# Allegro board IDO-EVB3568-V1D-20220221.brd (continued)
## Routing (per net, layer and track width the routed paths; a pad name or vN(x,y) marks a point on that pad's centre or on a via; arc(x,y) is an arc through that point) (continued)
GMAC0_TXD1_: length 62.4
  TOP w0.127: v2(92.43,56.72) 92.58,56.57 92.58,54.48 90.81,52.7 90.81,52.32 90.17,51.69 90.17,30.73 85.39,25.96 v2(84.96,25.96)
  BOTTOM w0.127: U24.17 109.57,70.27 110.67,69.16 110.67,65.73 107.17,62.23 103.19,62.23 102.81,62.61 101.41,62.61 100.78,61.98 98.3,61.98 93.04,56.72 v2(92.43,56.72) ; R198.2 v2(84.96,25.96)
GMAC0_TXD2: length 2
  TOP w0.127: M5.42 78.39,23.25 v2(78.92,22.72)
  BOTTOM w0.127: v2(78.92,22.72) 78.92,23.11 78.99,23.19 R201.1
GMAC0_TXD2_: length 67.1
  TOP w0.127: v2(90.91,55.65) 90.55,55.3 90.55,54.74 89.28,53.47 89.28,53.09 88.65,52.45 88.65,34.04 80.39,25.78 79.5,25.78 v2(78.99,25.27)
  BOTTOM w0.127: R201.2 v2(78.99,25.27) ; v2(90.91,55.65) 92.35,55.65 98.42,61.72 100.88,61.72 101.52,62.36 102.71,62.36 103.09,61.98 107.28,61.98 110.92,65.62 110.92,69.29 109.55,70.67 U24.16
GMAC0_TXD3: length 1.9
  TOP w0.127: v2(79.88,22.74) 79.39,23.24 M5.43
  BOTTOM w0.127: R202.1 80.01,23.27 79.88,23.15 v2(79.88,22.74)
GMAC0_TXD3_: length 67.3
  TOP w0.127: v2(79.63,25.25) 79.9,25.53 80.52,25.53 88.9,33.91 88.9,52.32 89.53,52.96 89.53,53.34 91.03,54.84 v2(91.03,55.09)
  BOTTOM w0.127: U24.15 109.53,71.07 111.18,69.42 111.18,65.52 107.38,61.72 102.98,61.72 102.6,62.1 101.62,62.1 100.99,61.47 98.55,61.47 92.2,55.12 91.06,55.12 v2(91.03,55.09) ; v2(79.63,25.25) 80.01,24.87 R202.2
GMAC0_TXEN: length 2.5
  TOP w0.127: v2(86.11,25.12) 85.83,25.12 85.39,24.68 M5.49
  BOTTOM w0.127: v2(86.11,25.12) 86.13,25.1 R204.1
GMAC0_TXEN_: length 60.5
  TOP w0.127: v2(92.68,57.86) 92.84,57.71 92.84,54.36 91.06,52.58 91.06,52.2 90.42,51.56 90.42,30.48 86.38,26.44 86.38,26.24 v2(86.11,25.96)
  BOTTOM w0.127: v2(92.68,57.86) 93.42,57.86 98.04,62.48 100.57,62.48 101.2,63.12 103.02,63.12 103.4,62.74 106.96,62.74 110.16,65.94 110.16,68.81 109.5,69.47 U24.19 ; R204.2 v2(86.11,25.96)
GMAC1_INT/PMEB_GPIO3_C1: length 8.9
  TOP w0.127: M5.110 87.39,69.58 87.96,69.01 93.81,69.01 v2(94.5,68.33)
  BOTTOM w0.127: v2(94.5,68.33) 94.5,68.06 94.66,67.9 R262.2
GMAC1_MCLKINOUT_M1: length 49.5
  TOP w0.127: v2(94.11,50.92) 93.22,50.03 93.22,41.91 93.73,41.4 93.73,38.48 94.36,37.85 94.36,37.21 95.33,36.24 M5.70
  BOTTOM w0.127: v2(94.11,50.92) 94.33,50.92 95.25,51.84 95.25,56.26 99.19,60.2 108.08,60.2 112.75,64.87 112.75,67.64 113.13,68.02 C194.2 113.18,68.02 113.67,68.51 113.78,68.51 114.15,68.88 R241.1 114.81,68.88 114.82,68.88 R240.1
GMAC1_MDC_M1: length 72
  TOP w0.127: M5.73 95.5,39.24 v2(95.25,39.24)
  BOTTOM w0.127: v2(95.25,39.24) 96.9,39.24 100.84,43.18 110.11,43.18 111.51,41.78 114.68,41.78 115.06,41.4 116.59,41.4 119.9,44.72 128.92,44.72 132.08,47.88 132.08,63.63 128.52,67.18 128.52,68.58 125.88,71.22 124.82,71.22 124.46,70.87 124.46,70.51 124.14,70.19 U25.13
GMAC1_MDIO_M1: length 72.2
  TOP w0.127: M5.72 95.11,38.24 94.73,38.62 v2(94.73,39.49)
  BOTTOM w0.127: v2(94.73,39.49) 94.73,39.88 95.11,40.26 97.16,40.26 100.58,43.69 110.36,43.69 111.76,42.29 114.93,42.29 115.32,41.91 116.33,41.91 119.63,45.21 119.66,45.21 119.67,45.22 128.66,45.22 131.57,48.13 131.57,63.39 128.02,66.95 128.02,68.33 125.93,70.41 125.22,70.41 R268.1 124.6,69.79 U25.14
GMAC1_RSTN_GPIO3_A6: length 8.5
  TOP w0.127: M5.121 76.39,70.7 75.33,71.75 v2(70.1,71.75)
  BOTTOM w0.127: v2(70.1,71.75) R267.1
GMAC1_RXCLK_M1: length 40.7
  TOP w0.127: v2(100.84,52.58) 100.71,52.45 100.71,51.05 100.08,50.42 98.04,50.42 97.86,50.24 M5.84
  BOTTOM w0.127: v2(100.84,52.58) 101.09,52.83 103.5,52.83 104.27,53.59 121.03,53.59 121.28,53.34 122.94,53.34 124.08,54.48 124.08,57.66 120.52,61.21 C211.2 119.81,61.83 119.76,61.88 R275.2
GMAC1_RXD0_M1: length 44.3
  TOP w0.127: M5.80 97.42,46.24 101.22,50.04 101.22,51.05 v2(101.47,51.31)
  BOTTOM w0.127: R271.2 121.67,63.91 122.19,63.39 122.19,61.33 124.97,58.55 124.97,54.1 123.19,52.32 104.39,52.32 103.38,51.31 v2(101.47,51.31)
GMAC1_RXD1_M1: length 42.5
  TOP w0.127: v2(101.71,50.8) 101.71,50.03 96.93,45.24 M5.79
  BOTTOM w0.127: R272.2 122.94,62.1 123.19,61.85 123.19,60.83 125.22,58.8 125.22,53.98 123.32,52.07 104.52,52.07 103.25,50.8 v2(101.71,50.8)
GMAC1_RXD2_M1: length 51.6
  TOP w0.127: M5.86 97.06,52.24 97.23,52.07 v2(99.95,52.07)
  BOTTOM w0.127: R273.2 122.96,64.34 123.57,63.73 123.57,60.83 128.27,56.13 128.27,49.4 127.11,48.25 103.5,48.25 100.46,51.29 100.46,51.56 v2(99.95,52.07)
GMAC1_RXD3_M1: length 51.4
  TOP w0.127: v2(99.95,51.44) 97.15,51.44 96.96,51.24 M5.85
  BOTTOM w0.127: R274.2 123.95,60.83 128.52,56.26 128.52,49.28 127.24,47.99 103.39,47.99 v2(99.95,51.44)
GMAC1_RXDV_CRS_M1: length 43.6
  TOP w0.127: v2(101.97,51.82) 101.97,51.42 102.11,51.28 102.11,49.91 96.43,44.24 M5.78
  BOTTOM w0.127: v2(101.97,51.82) 103.5,51.82 104.27,52.58 123.06,52.58 124.71,54.23 124.71,58.29 121.28,61.72 R276.2
GMAC1_TXCLK_M1: length 4.3
  TOP w0.127: M5.87 97.51,53.24 97.79,52.96 v2(98.83,52.96)
  BOTTOM w0.127: R253.1 99.06,52.32 99.27,52.53 C494.2 v2(98.83,52.96)
GMAC1_TXCLK_M1_: length 54.8
  BOTTOM w0.127: U25.20 124.25,67.39 125.35,66.29 125.35,60.83 129.29,56.9 129.29,48.77 127.76,47.24 102.49,47.24 101.22,48.51 101.22,49.15 100.2,50.16 C197.2 99.62,50.58 R253.2
GMAC1_TXD0_M1: length 3.9
  TOP w0.127: v2(98.93,49.15) 98.55,49.53 97.79,49.53 97.5,49.24 M5.83
  BOTTOM w0.127: R244.1 99.19,48.9 v2(98.93,49.15)
GMAC1_TXD0_M1_: length 56.5
  BOTTOM w0.127: U25.18 125.23,68.19 130.33,63.09 130.33,48.41 128.16,46.24 100.55,46.24 99.21,47.58 R244.2
GMAC1_TXD1_M1: length 2.9
  TOP w0.127: M5.82 97.39,48.24 v2(98.17,49.02)
  BOTTOM w0.127: R245.1 v2(98.17,49.02)
GMAC1_TXD1_M1_: length 58.6
  BOTTOM w0.127: R245.2 98.2,47.58 99.79,45.99 128.28,45.99 130.63,48.34 130.63,63.17 125.21,68.59 U25.17
GMAC1_TXD2_M1: length 5.3
  TOP w0.127: M5.89 97.18,55.24 98.17,54.24 v2(98.17,53.85)
  BOTTOM w0.127: v2(98.17,53.85) 98.17,52.29 97.79,51.91 R248.1
GMAC1_TXD2_M1_: length 63.7
  BOTTOM w0.127: R248.2 97.79,50.2 97.54,49.94 97.54,47.24 97.79,46.99 98.3,46.99 99.56,45.73 128.41,45.73 130.94,48.26 130.94,63.25 125.19,68.99 U25.16
GMAC1_TXD3_M1: length 2
  TOP w0.127: v2(97.54,53.85) 97.15,54.24 M5.88
  BOTTOM w0.127: R249.1 v2(97.54,53.85)
GMAC1_TXD3_M1_: length 66.9
  BOTTOM w0.127: R249.2 97.54,52.1 97.28,51.85 97.28,47.12 97.66,46.74 98.19,46.74 99.45,45.48 128.54,45.48 131.22,48.16 131.22,63.35 125.17,69.39 U25.15
GMAC1_TXEN_M1: length 5.2
  TOP w0.127: M5.81 97.78,47.24 v2(99.69,49.15)
  BOTTOM w0.127: v2(99.69,49.15) 100.2,48.64 R252.1
GMAC1_TXEN_M1_: length 54.5
  BOTTOM w0.127: R252.2 100.2,47.37 101.08,46.49 128.03,46.49 130.02,48.49 130.02,57.43 126.11,61.34 126.11,66.8 125.12,67.79 U25.19
HDMI_TX_CEC_PORT: length 7.5
  TOP w0.127: J18.13 31.15,91.16 32.26,90.04 D108.2 32.77,89 32.77,88.01 32.38,87.63 Q5.3
HDMI_TX_CLKN: length 24
  TOP w0.102: M5.153 44.39,70.29 44.06,70.62 v2(44.06,70.99) ; v2(30.73,85.47) 30.49,85.72 30.49,85.86 30.75,86.12 L26.2
  VCC w0.102: v2(30.73,85.47) 30.61,85.34 30.61,82.73 37.97,75.36 40.77,75.36 43.61,72.52 43.61,72.09 43.9,71.8 43.9,71.15 v2(44.06,70.99)
HDMI_TX_CLKN_: length 4.9
  TOP w0.102: J18.12 30.65,91.34 30.35,91.05 30.35,90.3 30.46,90.19 D48.6 D48.5 30.46,88.54 30.75,88.25 L26.3
HDMI_TX_CLKP: length 23.9
  TOP w0.102: v2(43.43,70.99) 43.43,70.74 43.39,70.69 M5.154 ; v2(29.97,85.47) 30.22,85.72 30.22,85.86 29.95,86.12 L26.1
  VCC w0.102: v2(29.97,85.47) 30.3,85.14 30.3,82.6 37.85,75.06 40.64,75.06 43.31,72.39 43.31,71.96 43.59,71.67 43.59,71.15 v2(43.43,70.99)
HDMI_TX_CLKP_: length 5
  TOP w0.102: L26.4 29.95,88.37 30.09,88.51 30.09,88.65 29.96,88.78 D48.4 D48.7 30.12,90.01 30.12,90.91 29.65,91.38 J18.10
HDMI_TX_D0N: length 23.9
  TOP w0.102: v2(42.25,70.93) 42.25,70.66 42.39,70.51 M5.155 ; L25.2 28.97,86.12 28.71,85.86 28.71,85.72 v2(28.96,85.47)
  VCC w0.102: v2(42.25,70.93) 42.04,71.14 42.04,72.26 40.08,74.22 37.46,74.22 28.73,82.96 28.73,85.24 v2(28.96,85.47)
HDMI_TX_D0N_: length 4.9
  TOP w0.102: L25.3 28.96,87.98 D48.2 D48.9 28.96,90.09 28.7,90.35 28.7,90.93 29.15,91.38 J18.9
HDMI_TX_D0P: length 23.9
  TOP w0.102: M5.156 41.39,70.6 41.53,70.74 v2(41.53,70.93) ; L25.1 28.18,86.12 28.44,85.86 28.44,85.72 v2(28.19,85.47)
  VCC w0.102: v2(41.53,70.93) 41.73,71.14 41.73,72.14 39.96,73.91 37.34,73.91 28.42,82.83 28.42,85.24 v2(28.19,85.47)
HDMI_TX_D0P_: length 5
  TOP w0.102: J18.7 28.15,91.36 28.46,91.04 D48.10 D48.1 28.46,88.51 28.57,88.4 28.57,88.26 28.28,87.97 L25.4
HDMI_TX_D1N: length 23.5
  TOP w0.102: M5.157 40.39,70.61 40.21,70.78 v2(40.21,70.99) ; v2(27.18,85.47) 26.93,85.72 26.93,85.86 27.2,86.12 L24.2
  VCC w0.102: v2(27.18,85.47) 26.95,85.24 26.95,83.08 36.96,73.08 39.12,73.08 40.01,72.18 40.01,71.2 v2(40.21,70.99)
HDMI_TX_D1N_: length 5.1
  TOP w0.102: L24.3 27.2,88.12 26.91,88.41 D47.5 D47.6 26.91,90.53 27.65,91.27 J18.6
HDMI_TX_D1P: length 23.5
  TOP w0.102: M5.158 39.39,70.63 39.5,70.74 v2(39.5,70.99) ; L24.1 26.4,86.12 26.66,85.86 26.66,85.72 v2(26.42,85.47)
  VCC w0.102: v2(39.5,70.99) 39.7,71.2 39.7,72.06 38.99,72.77 36.83,72.77 26.64,82.96 26.64,85.24 v2(26.42,85.47)
HDMI_TX_D1P_: length 5.1
  TOP w0.102: J18.4 26.65,91.34 26.86,91.13 26.86,90.86 26.59,90.6 26.59,90.21 26.41,90.03 D47.7 D47.4 26.41,88.78 26.64,88.55 26.64,88.35 26.4,88.11 L24.4
HDMI_TX_D2N: length 23
  TOP w0.102: v2(25.4,85.47) 25.15,85.72 25.15,85.86 25.42,86.12 L23.2 ; v2(38.31,70.93) 38.31,70.66 38.39,70.58 M5.159
  VCC w0.102: v2(25.4,85.47) 25.17,85.24 25.17,83.21 36.45,71.93 37.82,71.93 38.1,71.65 38.1,71.14 v2(38.31,70.93)
HDMI_TX_D2N_: length 5
  TOP w0.102: J18.3 26.15,91.3 25.91,91.06 25.78,91.06 25.41,90.69 D47.9 D47.2 25.41,87.98 L23.3
HDMI_TX_D2P: length 23
  TOP w0.102: v2(24.64,85.47) 24.88,85.72 24.88,85.86 24.62,86.12 L23.1 ; v2(37.59,70.93) 37.59,70.74 37.39,70.54 M5.160
  VCC w0.102: v2(37.59,70.93) 37.8,71.14 37.8,71.53 37.7,71.63 36.32,71.63 24.87,83.08 24.87,85.24 v2(24.64,85.47)
HDMI_TX_D2P_: length 4.9
  TOP w0.102: J18.1 25.13,92.59 25.13,90.28 24.91,90.06 D47.10 D47.1 24.91,88.41 24.62,88.12 L23.4
HDMI_TX_HPD_PORT: length 13.9
  TOP w0.127: J18.19 34.15,91.2 34.42,90.93 35.02,90.93 D111.2 37.11,89.51 37.97,88.65 37.97,82.8 38.18,82.6 R86.1 R85.2
HDMI_TX_HPDIN: length 16.8
  TOP w0.127: R85.1 39.04,78.69 40.64,77.09 42.19,77.09 48.41,70.87 49.02,70.87 49.39,70.5 M5.148
HDMI_TXDDC_SCL_PORT: length 9.4
  TOP w0.127: J18.15 32.15,90.79 32.89,90.04 33.53,90.04 33.66,89.92 D109.2 33.15,89 33.15,88.01 32.97,87.84 R82.2 32.97,86.87 33.1,86.74 34.31,86.74 34.54,86.51 Q3.3
HDMI_TXDDC_SDA_PORT: length 9.3
  TOP w0.127: Q4.3 36.7,86.87 36.19,87.38 R84.2 35.86,88.85 35.2,89.51 D110.2 34.68,89.51 33.89,90.3 33.15,90.3 32.65,90.8 J18.16
HDMITX_CEC_M0: length 22.7
  TOP w0.127: Q5.2 32.88,83.76 31.96,82.83 R87.2 32.59,82.17 34.42,82.17 40.26,76.33 41.78,76.33 46.39,71.72 M5.151
HOST_WAKE_BT: length 5.2
  TOP w0.127: U23.6 118.31,54.25 119.2,53.36 ; R162.2 121.49,53.36 121.01,53.85 119.69,53.85 119.2,53.36 ; 119.2,53.36 R164.1
HOST_WAKE_BT_H_GPIO3_A2: length 81.3
  TOP w0.127: v2(102.06,77.04) 102.82,76.28 102.82,76.02 103.53,75.31 111.76,75.31 113.28,73.79 113.28,68.71 114.71,67.28 114.71,66.52 115.9,65.33 117.68,65.33 v2(117.86,65.15) ; v2(93.51,67.57) 93.13,67.94 87.76,67.94 87.25,68.45 73.03,68.45 72.39,69.09 M5.125 ; R162.1 122.78,53.34 123.02,53.58 v2(123.02,54.53)
  BOTTOM w0.127: v2(123.02,54.53) 118.19,54.53 116.71,56.01 116.71,63.63 117.86,64.77 v2(117.86,65.15) ; v2(102.06,77.04) 101.75,77.34 97.66,77.34 96.14,75.82 96.14,70.61 94.11,68.58 94.11,67.78 93.9,67.57 v2(93.51,67.57)
HP_DET_H_GPIO0_C5: length 41.7
  TOP w0.127: M5.24 60.39,22.67 60.96,22.1 66.04,22.1 67.74,20.4 83.99,20.4 88.82,20.4 89.28,19.94 91.9,19.94 v2(92.08,19.76) ; v2(94.61,15.88) R72.2 C82.2 R74.1
  BOTTOM w0.127: v2(94.61,15.88) 94.61,16.38 93.47,17.53 93.47,17.91 92.08,19.3 v2(92.08,19.76)
HP_SNS: length 58.3
  TOP w0.254: R77.1 99.31,15.24 96.14,18.41 91.44,18.41 91.26,18.24 86.89,18.24 86.18,17.53 83.5,17.53 82.79,18.24 66.85,18.24 64.9,20.19 60.17,20.19 59.46,20.9 48.31,20.9 46.39,22.83 M5.10
HPL_OUT: length 58.4
  TOP w0.254: v2(92.43,17.91) 92.3,18.03 91.74,18.03 91.57,17.86 87.07,17.86 86.36,17.14 83.34,17.14 82.63,17.86 66.6,17.86 64.64,19.81 60.01,19.81 59.3,20.52 48.07,20.52 48.07,20.52 47.8,20.52 45.39,22.94 M5.9
  BOTTOM w0.254: C86.2 R73.1 94.49,12.45 93.6,13.34 93.6,16.21 92.43,17.37 v2(92.43,17.91)
HPR_OUT: length 60.4
  TOP w0.254: M5.11 47.39,22.84 48.95,21.28 59.61,21.28 60.33,20.57 65.15,20.57 67.11,18.62 82.95,18.62 83.66,17.91 85.98,17.91 86.69,18.62 91.01,18.62 91.19,18.8 97.28,18.8 101.55,14.53 C89.2 R76.1
HUB_RST_: length 5.1
  BOTTOM w0.127: U8.40 82.63,55.83 82.04,55.24 C60.2 R48.2 R39.2
I2C1_SCL: length 76.3
  TOP w0.127: v2(78.89,45.85) 81.41,43.33 81.41,43.05 v2(85.22,39.24) 85.85,38.61 85.85,35.43 78.99,28.57 71.12,28.57 70.1,27.56 67.94,27.56 67.18,26.8 67.18,25.66 68.39,24.46 M5.32 ; v2(114.13,40.78) 114.13,41.76 114.63,42.27 R316.2 R313.1
  BOTTOM w0.127: R344.1 v2(78.89,45.85) ; v2(114.13,40.78) 110.73,40.78 109.09,42.42 101.22,42.42 95.12,36.32 89.4,36.32 86.05,39.67 85.65,39.67 v2(85.22,39.24)
I2C1_SCL_RTC: length 2.2
  TOP w0.127: U34.6 116.42,42.64 116.07,42.29 R316.1
I2C1_SDA: length 83.4
  TOP w0.127: R312.1 R317.2 120.19,44.43 118.97,43.21 v2(118.97,42.24) ; M5.33 69.39,23.99 69,24.38 68.83,24.38 67.56,25.65 67.56,26.67 68.2,27.3 70.36,27.3 71.37,28.32 79.12,28.32 86.11,35.31 86.11,38.99 v2(85.85,39.24) 81.79,43.31 81.79,43.96 v2(78.89,46.86)
  BOTTOM w0.127: v2(85.85,39.24) 89.03,36.07 95.25,36.07 101.35,42.16 108.84,42.16 110.62,40.39 115.3,40.39 117.12,40.39 v2(118.97,42.24) ; R343.1 v2(78.89,46.86)
I2C1_SDA_RTC: length 2.3
  TOP w0.127: U34.5 118.32,43.29 118.96,43.93 118.96,44.06 119.33,44.43 R317.1
I2C2_SCL_M0: length 16.6
  TOP w0.127: M5.34 70.39,23.99 69.62,24.77 68.83,24.77 67.94,25.65 67.94,26.29 v2(68.45,26.8)
  BOTTOM w0.127: v2(68.45,26.8) 67.18,28.07 67.18,29.84 66.67,30.35 66.67,32.38 67.06,32.77 67.06,33.4 66.29,34.16 65.18,34.16 65.02,34.32 R320.1 65.05,34.75 65.42,35.12 65.52,35.12 66.02,35.61 R318.1
I2C2_SDA_M0: length 17.2
  TOP w0.127: M5.35 71.39,23.99 70.36,25.02 68.96,25.02 68.45,25.53 v2(68.45,26.16)
  BOTTOM w0.127: R319.1 R321.1 64.03,34.75 64.87,33.91 66.17,33.91 66.8,33.27 66.8,32.89 66.42,32.51 66.42,30.23 66.93,29.72 66.93,27.69 v2(68.45,26.16)
I2C3_SCL_M1: length 70.7
  TOP w0.127: v2(78.47,72.03) 78.71,72.26 79.86,72.26 80.57,71.55 82.35,71.55 83.39,70.51 M5.114 ; v2(73.03,27.79) 73.76,27.05 75.82,27.05 76.33,27.56 79.5,27.56 86.74,34.8 86.74,34.82 86.87,34.95 86.87,62.99 85.47,64.39 79.38,64.39 78.49,65.28 77.39,65.28 v2(77.14,65.53)
  BOTTOM w0.127: v2(77.14,65.53) 77.14,68 78.23,69.09 78.23,71.12 78.47,71.36 v2(78.47,72.03) 78.47,72.58 R109.1 ; R113.1 v2(73.03,27.79)
I2C3_SDA_M1: length 68.1
  TOP w0.127: v2(71.88,27.79) 72.87,26.8 75.95,26.8 76.45,27.3 79.63,27.3 87.12,34.8 87.12,54.23 90.3,57.4 90.3,61.9 v2(89.69,62.51) ; v2(80.77,71.98) 83.21,71.98 84.39,70.81 M5.113 84.39,69.41 84.81,68.99 87.48,68.99 87.76,68.71 90.63,68.71 v2(90.73,68.61)
  BOTTOM w0.127: v2(89.69,62.51) 89.97,62.79 89.97,62.79 90.73,63.55 v2(90.73,68.61) ; R114.1 v2(71.88,27.79) ; v2(80.77,71.98) R110.1
I2C4_SCL_M0: length 2.6
  TOP w0.127: v2(95.3,42.55) 95.61,42.24 M5.76
  BOTTOM w0.127: R147.1 R144.1 v2(95.3,42.55)
I2C4_SDA_M0: length 2.6
  TOP w0.127: M5.77 95.73,43.24 v2(95.3,43.66)
  BOTTOM w0.127: R146.1 R145.1 v2(95.3,43.66)
I2C5_SCL-HDMI: length 20.5
  TOP w0.127: Q3.2 35.04,83.45 34.97,83.38 R81.2 34.97,81.99 40.39,76.58 41.91,76.58 47.39,71.1 M5.150
I2C5_SDA-HDMI: length 20
  TOP w0.127: M5.149 48.39,70.48 42.04,76.83 40.51,76.83 37.13,80.22 R83.2 37.13,83.38 37.2,83.45 Q4.2
LAN0_A+: length 24.4
  TOP w0.102: v2(103.76,78.61) 103.96,78.82 104.11,78.82 104.27,78.66 104.27,77.78 105.95,76.1 111.02,76.1 111.86,76.94 111.86,82.14 112.65,82.93 J30.2
  BOTTOM w0.102: v2(103.76,78.61) 103.95,78.42 D72.6 104.2,77.27 104.2,76.89 103.27,75.97 R190.2
LAN0_A-: length 24.4
  TOP w0.102: v2(103.76,79.25) 103.96,79.04 104.2,79.04 104.5,78.75 104.5,77.88 106.05,76.33 110.93,76.33 111.63,77.03 111.63,82.24 112.42,83.03 112.42,84.43 112.07,84.78 111.38,84.78
  BOTTOM w0.102: 103.95,80.07 103.95,79.44 v2(103.76,79.25) ; 103.95,80.07 D72.1 ; 103.95,80.07 104.42,79.6 104.42,76.8 103.89,76.26 103.89,76.12 R189.2
LAN0_B+: length 28.3
  TOP w0.102: v2(106.17,79.25) 105.97,79.04 105.54,79.04 105.31,78.81 105.31,78.14 106.59,76.86 110.64,76.86 111.23,77.44 111.23,82.26 110.24,83.25 110.24,85.6 108.94,86.89 108.94,88.37 109.09,88.52 110.01,88.52 110.11,88.42 J30.4
  BOTTOM w0.102: D72.3 105.85,80.07 ; 105.85,80.07 105.85,79.57 v2(106.17,79.25) ; 105.85,80.07 105.38,79.6 105.38,76.07 105.28,75.97 R188.2
LAN0_B-: length 28.3
  TOP w0.102: 106.3,84.78 106.3,88.01 106.81,88.52 108.46,88.52 108.71,88.27 108.71,86.8 110.01,85.5 110.01,83.16 111,82.17 111,77.54 110.55,77.09 106.68,77.09 105.54,78.23 105.54,78.71 105.64,78.82 105.97,78.82 v2(106.17,78.61)
  BOTTOM w0.102: R187.2 105.89,75.97 105.61,76.26 105.61,77.27 D72.4 105.85,78.29 v2(106.17,78.61)
LAN0_C+: length 19.4
  TOP w0.102: J30.5 109.12,84.78 109.22,84.88 109.22,85.6 108.47,86.35 107.94,86.35 107.8,86.21 107.8,83.03 110.62,80.21 110.62,78.11 110.13,77.62 108.86,77.62 107.66,78.82 107.52,78.82 v2(107.31,78.61)
  BOTTOM w0.102: R186.2 107.53,75.97 107.7,76.13 107.7,77.46 D71.6 107.63,78.29 v2(107.31,78.61)
LAN0_C-: length 19.6
  TOP w0.102: v2(107.31,79.25) 107.52,79.04 107.76,79.04 108.95,77.85 110.04,77.85 110.39,78.2 110.39,80.11 107.57,82.93 J30.6
  BOTTOM w0.102: 107.63,79.94 107.63,79.57 v2(107.31,79.25) ; 107.63,79.94 D71.1 ; 107.63,79.94 108.11,79.47 108.11,76.91 107.95,76.76 107.95,76.33 R185.2
LAN0_D+: length 16.7
  TOP w0.102: J30.8 105.03,83.19 109.17,79.04 109.52,79.04 v2(109.73,79.25)
  BOTTOM w0.102: v2(109.73,79.25) 109.54,79.44 D71.3 109.16,80.22 109.06,80.12 109.06,76.87 109.59,76.33 109.59,76.19 R184.2
LAN0_D-: length 16.7
  TOP w0.102: v2(109.73,78.61) 109.52,78.82 109.07,78.82 104.8,83.09 104.8,86.08 104.39,86.49 103.38,86.49 103.03,86.14 103.03,85.51 103.76,84.78
  BOTTOM w0.102: R183.2 110.34,75.97 109.54,76.77 D71.4 109.54,78.42 v2(109.73,78.61)
LAN1_A+: length 29.9
  TOP w0.102: v2(120.91,80.9) 120.66,80.66 120.43,80.66 120.17,80.4 120.17,79.92 121.57,78.51 125.5,78.51 129.95,82.96 132.05,82.96 132.61,83.52 J31.2
  BOTTOM w0.102: R237.2 118.05,73.91 118.27,74.13 118.27,74.13 118.28,74.14 118.28,74.53 118.78,75.03 119.48,75.03 120.59,76.14 D74.6 120.83,76.62 120.83,77.47 120.11,78.19 120.11,80.3 120.43,80.62 120.63,80.62 v2(120.91,80.9)
LAN1_A-: length 29.9
  TOP w0.102: J31.3 131.34,86 131.57,86.23 132.33,86.23 132.38,86.18 132.38,83.62 131.95,83.19 129.85,83.19 125.41,78.74 121.67,78.74 120.4,80.01 120.4,80.3 120.52,80.43 120.66,80.43 v2(120.91,80.18)
  BOTTOM w0.102: R236.2 118.5,74.23 118.5,74.43 118.87,74.8 119.58,74.8 120.44,75.67 120.96,75.67 121.06,75.77 121.06,75.78 121.06,77.57 120.34,78.29 120.34,78.82 D74.1 120.34,79.32 120.34,80.21 120.52,80.39 120.7,80.39 v2(120.91,80.18)
LAN1_B+: length 30.5
  TOP w0.102: v2(121.79,80.18) 122.04,80.43 122.2,80.43 122.3,80.32 122.3,79.63 122.68,79.25 125.35,79.25 130.18,84.07 130.18,85.47 128.75,86.89 128.75,88.11 128.64,88.22 128.64,88.38 128.78,88.52 130.68,88.52 131.19,88.01 131.19,87.12 130.81,86.74 130.66,86.74 J31.4
  BOTTOM w0.102: R235.2 120.15,74.19 120.29,74.33 120.29,74.77 120.71,75.18 121.54,75.18 122.01,75.66 122.01,77.56 122.68,78.23 122.68,78.88 D74.3 122.74,79.32 122.74,79.83 122.16,80.41 122.02,80.41 v2(121.79,80.18)
LAN1_B-: length 30.5
  TOP w0.102: J31.7 126.26,87.91 126.87,88.52 128.02,88.52 128.52,88.01 128.52,86.8 129.95,85.38 129.95,84.17 125.25,79.48 122.78,79.48 122.53,79.72 122.53,80.42 122.29,80.66 122.04,80.66 v2(121.79,80.9)
  BOTTOM w0.102: v2(121.79,80.9) 122.06,80.63 122.25,80.63 122.97,79.92 122.97,78.19 122.24,77.47 122.24,76.62 D74.4 122.25,76.13 122.25,75.57 121.63,74.96 120.8,74.96 120.52,74.68 120.52,74.47 R234.2
LAN1_C+: length 19.9
  TOP w0.102: J31.5 128.8,85.57 128.52,85.85 127.89,85.85 127.76,85.72 127.76,82.55 125.22,80.01 123.99,80.01 123.57,80.43 123.43,80.43 v2(123.22,80.21)
  BOTTOM w0.102: R233.2 122.17,74.59 122.17,74.59 122.21,74.63 122.21,74.83 122.91,75.54 123.98,75.54 124.27,75.83 D73.6 124.52,76.62 124.52,77.67 123.79,78.39 123.79,80.23 123.63,80.39 123.39,80.39 v2(123.22,80.21)
LAN1_C-: length 19.9
  TOP w0.102: v2(123.19,80.9) 123.43,80.66 123.67,80.66 124.08,80.24 125.13,80.24 127.53,82.64 J31.6
  BOTTOM w0.102: R232.2 122.53,74.19 122.38,74.34 122.38,74.48 122.4,74.5 122.4,74.5 122.43,74.54 122.43,74.74 123.01,75.31 124.08,75.31 124.44,75.67 124.65,75.67 124.74,75.77 124.74,77.76 124.27,78.24 D73.1 124.02,79.32 124.02,80.32 123.7,80.64 123.44,80.64 v2(123.19,80.9)
LAN1_D+: length 19.5
  TOP w0.102: v2(124.33,80.9) 124.59,81.15 124.59,81.72 122.2,84.11 122.2,85.31 123.25,86.36 124.89,86.36 124.99,86.46 J31.8
  BOTTOM w0.102: v2(124.33,80.9) 124.59,80.64 124.59,80.39 124.94,80.04 126.14,80.04 126.42,79.76 126.42,79.32 D73.3 126.17,78.17 125.7,77.69 125.7,75.35 125.41,75.06 124.76,75.06 124.3,74.59 124.3,74.27 124.22,74.19 R231.2
LAN1_D-: length 19.6
  TOP w0.102: J31.9 124.52,85.58 124.52,86.03 124.41,86.13 123.34,86.13 122.43,85.22 122.43,84.2 124.82,81.81 124.82,81.13 v2(125.05,80.9)
  BOTTOM w0.102: R230.2 124.67,74.19 124.53,74.33 124.53,74.5 124.86,74.83 125.5,74.83 125.93,75.26 125.93,76.13 D73.4 125.93,76.62 125.93,77.6 126.65,78.32 126.65,79.85 126.24,80.26 125.04,80.26 124.82,80.49 124.82,80.67 v2(125.05,80.9)
LCM_VIO_EN: length 97.5
  TOP w0.127: v2(90.81,7.49) 91.19,7.87 91.19,10.81 90.17,11.82 v2(90.17,12.22) 89.68,12.71 Q7.1 ; v2(49.53,12.62) 49.14,13.01 Q10.1 ; v2(78.61,40.01) 79.12,39.5 79.12,30.73 v2(78.61,30.23)
  BOTTOM w0.127: v2(90.17,12.22) 90.58,12.22 90.89,12.53 90.89,12.99 91.31,13.41 91.31,22.35 89.53,24.13 89.53,25.15 88.9,25.78 88.9,26.42 87.63,27.69 84.71,27.69 82.04,30.35 79.39,30.35 79.26,30.23 v2(78.61,30.23) ; R359.1 v2(78.61,40.01) 81.07,40.01 82,40.93 U38.15 ; v2(49.53,12.62) 52.65,12.62 53.72,11.56 54.61,11.56 55.4,10.77 70.84,10.77 71.63,11.56 76.18,11.56 77.09,10.65 77.09,7.62 77.22,7.49 v2(90.81,7.49)
LVDS0_CLKN: length 28.7
  TOP w0.102: v2(23.58,14.24) 23.82,14 23.82,13.65 23.69,13.51 D68.5 D68.6 23.69,12.13 23.82,11.99 23.82,11.29 24.31,10.79 25.15,10.79 26.04,9.91 26.04,8.36 25.93,8.26 25.27,8.26 25.17,8.36 J26.15 ; U17.27 18.79,24.31 18.66,24.17 18.23,24.17 15.46,21.4 15.46,18.85 v2(15.28,18.67)
  GND w0.102: v2(23.58,14.24) 23.79,14.44 23.79,14.95 22.99,15.75 16.51,15.75 15.42,16.84 15.42,18.52 v2(15.28,18.67)
LVDS0_CLKP: length 28.7
  TOP w0.102: U17.28 18.79,23.81 18.65,23.94 18.32,23.94 15.69,21.31 15.69,18.85 v2(15.88,18.67) ; J26.16 25.17,7.93 25.27,8.03 26.03,8.03 26.26,8.27 26.26,10 25.24,11.02 24.41,11.02 24.05,11.38 24.05,11.99 24.19,12.12 D68.7 D68.4 24.19,13.51 24.05,13.65 24.05,14 v2(24.3,14.24)
  GND w0.102: v2(24.3,14.24) 24.09,14.44 24.09,15.07 23.11,16.05 16.64,16.05 15.73,16.96 15.73,18.52 v2(15.88,18.67)
LVDS0_D0N: length 28.8
  TOP w0.102: J26.7 33.17,8.36 33.27,8.26 33.93,8.26 34.04,8.36 34.04,9.91 32.49,11.46 28.61,11.46 28.37,11.69 28.37,11.99 28.24,12.12 D66.9 D66.2 28.24,13.48 28.37,13.62 28.37,14.07 v2(28.13,14.32) ; U17.33 18.75,21.31 18.61,21.17 18.31,21.17 18.02,20.87 18.02,20.02 18.11,19.93 18.11,19.42 v2(17.95,19.26)
  GND w0.102: v2(28.13,14.32) 28.33,14.52 28.33,15.3 25.22,18.41 18.44,18.41 18.08,18.77 18.08,19.12 v2(17.95,19.26)
LVDS0_D0P: length 28.8
  TOP w0.102: v2(18.52,19.26) 18.34,19.44 18.34,20.02 18.24,20.12 18.24,20.78 18.41,20.94 18.59,20.94 18.73,20.81 U17.34 ; v2(28.84,14.32) 28.6,14.07 28.6,13.62 28.74,13.49 D66.1 D66.10 28.74,12.1 28.6,11.96 28.6,11.79 28.7,11.68 32.58,11.68 34.26,10 34.26,8.27 34.03,8.03 33.27,8.03 33.17,7.93 J26.8
  GND w0.102: v2(18.52,19.26) 18.39,19.12 18.39,18.9 18.57,18.72 25.35,18.72 28.64,15.43 28.64,14.52 v2(28.84,14.32)
LVDS0_D1N: length 29.3
  TOP w0.102: v2(17.11,18.59) 17.3,18.78 17.3,21.11 18.36,22.17 18.64,22.17 18.77,22.31 U17.31 ; J26.9 31.17,8.36 31.27,8.26 31.88,8.26 32,8.39 32,10.16 31.47,10.69 27.69,10.69 26.87,11.51 26.87,11.74 26.74,11.88 D66.6 D66.5 26.74,13.48 26.87,13.61 26.87,14.05 v2(26.63,14.29)
  GND w0.102: v2(26.63,14.29) 26.83,14.5 26.83,14.95 24.18,17.6 17.65,17.6 17.25,18.01 17.25,18.46 v2(17.11,18.59)
LVDS0_D1P: length 29.3
  TOP w0.102: v2(27.34,14.29) 27.1,14.05 27.1,13.62 27.24,13.48 D66.4 D66.7 27.24,11.88 27.1,11.74 27.1,11.61 27.79,10.92 31.57,10.92 32.23,10.25 32.23,8.29 31.97,8.03 31.27,8.03 31.17,7.93 J26.10 ; U17.32 18.78,21.81 18.65,21.94 18.45,21.94 17.53,21.01 17.53,18.75 v2(17.69,18.59)
  GND w0.102: v2(17.69,18.59) 17.55,18.46 17.55,18.14 17.78,17.91 24.31,17.91 27.14,15.07 27.14,14.5 v2(27.34,14.29)
LVDS0_D2N: length 29.9
  TOP w0.102: U17.29 18.73,23.31 18.6,23.17 18.29,23.17 16.44,21.32 16.44,19.62 v2(16.26,19.43) ; v2(25.08,14.24) 25.32,14 25.32,13.62 25.19,13.48 D68.2 D68.9 25.19,12.15 25.32,12.01 25.32,11.76 25.88,11.2 26.03,11.2 27.17,10.06 29.97,10.06 30.1,9.93 30.1,8.45 29.91,8.26 29.27,8.26 29.17,8.36 J26.11
  GND w0.102: v2(16.26,19.43) 16.4,19.28 16.4,17.51 17.14,16.76 23.83,16.76 25.29,15.3 25.29,14.44 v2(25.08,14.24)
LVDS0_D2P: length 29.9
  TOP w0.102: v2(16.86,19.43) 16.67,19.62 16.67,21.22 18.39,22.94 18.64,22.94 18.78,22.81 U17.30 ; v2(25.8,14.24) 25.55,14 25.55,13.6 25.69,13.46 D68.1 D68.10 25.69,12.14 25.55,12.01 25.55,11.85 25.98,11.43 26.12,11.43 27.26,10.29 30.07,10.29 30.33,10.03 30.33,8.36 30,8.03 29.27,8.03 29.17,7.93 J26.12
  GND w0.102: v2(16.86,19.43) 16.71,19.28 16.71,17.63 17.27,17.07 23.95,17.07 25.59,15.43 25.59,14.44 v2(25.8,14.24)
LVDS0_D3N: length 29.2
  TOP w0.102: v2(14.26,19.43) 14.45,19.62 14.45,21.48 18.13,25.17 18.37,25.17 18.51,25.31 U17.25 ; J26.17 23.17,8.36 23.27,8.26 23.9,8.26 24,8.36 24,9.91 22.96,10.95 22.77,10.95 22.28,11.44 22.28,11.74 22.14,11.88 D69.9 D69.2 22.14,13.51 22.28,13.65 22.28,13.87 v2(22.03,14.11)
  GND w0.102: v2(14.26,19.43) 14.41,19.28 14.41,16.2 16,14.61 22.1,14.61 22.24,14.46 22.24,14.32 v2(22.03,14.11)
LVDS0_D3P: length 29.2
  TOP w0.102: v2(22.75,14.11) 22.51,13.87 22.51,13.65 22.64,13.51 D69.1 D69.10 22.64,11.88 22.51,11.74 22.51,11.53 22.86,11.18 23.06,11.18 24.23,10 24.23,8.27 24,8.03 23.27,8.03 23.17,7.93 J26.18 ; v2(14.86,19.43) 14.67,19.62 14.67,21.39 18.23,24.94 18.37,24.94 18.51,24.81 U17.26
  GND w0.102: v2(22.75,14.11) 22.54,14.32 22.54,14.59 22.22,14.91 16.13,14.91 14.71,16.33 14.71,19.28 v2(14.86,19.43)
LVDS1_CLKN: length 17.3
  TOP w0.102: J26.27 13.17,8.36 13.3,8.23 13.69,8.23 13.99,8.53 13.99,9.87 14.64,10.52 15.4,10.52 16.18,11.3 16.18,12.01 16.04,12.15 D70.9 D70.2 16.04,13.73 16.2,13.88 16.2,14.42 17.12,15.34 18.83,15.34 21.94,18.45 21.94,18.62 21.81,18.76 U17.41
LVDS1_CLKP: length 17.4
  TOP w0.102: J26.28 13.17,7.51 13.66,8 13.79,8 14.22,8.44 14.22,9.78 14.73,10.29 15.49,10.29 16.41,11.2 16.41,11.99 16.54,12.13 D70.10 D70.1 16.54,13.73 16.43,13.84 16.43,14.33 17.21,15.11 18.92,15.11 22.17,18.36 22.17,18.66 22.31,18.8 U17.42
LVDS1_D0N: length 15
  TOP w0.102: U17.47 24.81,18.76 24.94,18.62 24.94,18.54 20.78,14.38 20.78,13.86 20.64,13.73 D69.5 D69.6 20.64,12.07 20.78,11.94 20.78,11.35 22.1,10.03 22.1,8.58 21.78,8.26 21.52,8.26 21.44,8.17 21.3,8.17 21.17,8.3 J26.19
LVDS1_D0P: length 15
  TOP w0.102: J26.20 21.17,7.58 21.62,8.03 21.87,8.03 22.33,8.48 22.33,10.13 21.01,11.45 21.01,11.94 21.14,12.07 D69.7 D69.4 21.14,13.73 21.01,13.86 21.01,14.28 25.17,18.45 25.17,18.62 25.31,18.75 U17.48
LVDS1_D1N: length 14.9
  TOP w0.102: J26.21 19.17,8.36 19.4,8.13 19.56,8.13 20.07,8.64 20.07,10.29 19.23,11.12 19.23,11.74 19.09,11.88 D67.9 D67.2 19.09,13.48 19.25,13.63 19.25,13.76 23.94,18.45 23.94,18.63 23.81,18.77 U17.45
LVDS1_D1P: length 14.9
  TOP w0.102: J26.22 19.17,7.48 19.58,7.9 19.65,7.9 20.29,8.54 20.29,10.38 19.46,11.22 19.46,11.74 19.59,11.88 D67.10 D67.1 19.59,13.48 19.47,13.6 19.47,13.67 24.17,18.36 24.17,18.63 24.31,18.77 U17.46
LVDS1_D2N: length 15.5
  TOP w0.102: U17.43 22.81,18.8 22.94,18.66 22.94,18.46 19.06,14.58 17.97,14.58 17.73,14.34 17.73,13.62 17.59,13.48 D67.5 D67.6 17.59,11.88 17.73,11.74 17.73,11.48 18.03,11.18 18.03,8.64 17.66,8.26 17.59,8.26 17.5,8.17 17.36,8.17 17.17,8.36 J26.23
LVDS1_D2P: length 15.5
  TOP w0.102: U17.44 23.31,18.78 23.17,18.65 23.17,18.37 19.15,14.35 18.06,14.35 17.96,14.25 17.96,13.61 18.09,13.48 D67.4 D67.7 18.09,11.88 17.96,11.74 17.96,11.58 18.26,11.27 18.26,8.54 17.75,8.03 17.68,8.03 17.17,7.51 J26.24
LVDS1_D3N: length 18
  TOP w0.102: U17.39 20.81,18.82 20.94,18.68 20.94,18.52 18.52,16.1 16.74,16.1 14.69,14.05 14.69,13.87 14.54,13.73 D70.5 D70.6 14.54,12.09 14.68,11.95 14.68,11.65 14.46,11.43 13.39,11.43 11.99,10.03 11.99,8.44 11.81,8.26 11.62,8.26 11.52,8.16 11.37,8.16 11.17,8.36 J26.29
LVDS1_D3P: length 18.1
  TOP w0.102: U17.40 21.31,18.82 21.17,18.68 21.17,18.43 18.62,15.88 16.83,15.88 14.92,13.96 14.92,13.86 15.04,13.73 D70.4 D70.7 15.04,12.09 14.91,11.95 14.91,11.56 14.55,11.2 13.49,11.2 12.22,9.94 12.22,8.34 11.91,8.03 11.71,8.03 11.17,7.48 J26.30
LVDS_ON_: length 21
  TOP w0.127: v2(35.69,10.92) 35.51,10.92 R128.2 33.86,13.02 34.04,13.2 R127.2 34.49,13.79 34.56,13.72 Q8.2
  BOTTOM w0.127: J27.4 47.62,7.9 42.62,7.9 41.27,9.25 41.27,9.78 40.59,10.46 36.14,10.46 v2(35.69,10.92)
LVDS_PWM5: length 97.5
  TOP w0.127: v2(29.72,12.75) 29.86,12.9 U18.2 30.93,12.9 R130.1 ; v2(65.41,28.57) 63.58,28.57 59.39,24.38 M5.23
  BOTTOM w0.127: v2(65.41,28.57) 65.41,27.05 67.18,25.27 67.18,16.64 67.56,16.26 67.94,16.26 69.53,14.67 69.98,14.67 70.23,14.41 70.23,12.7 69.98,12.45 56.26,12.45 54.48,14.22 46.81,14.22 45.34,12.75 v2(29.72,12.75) 29.64,12.67 14.12,12.67 11.05,15.75 11.05,17.4 11.81,18.16 R102.1
LVDS_PWM5_: length 18.7
  TOP w0.127: v2(34.92,10.92) 34.16,10.92 32.84,12.25 U18.4 32.08,12.25 31.82,12.5 R130.2
  BOTTOM w0.127: J27.3 47.22,6.25 45.97,7.49 42.39,7.49 40.77,9.12 40.77,9.65 40.21,10.21 35.64,10.21 v2(34.92,10.92)
LVDS_VIO: length 8.6
  TOP w1.016: J25.6 43.34,11.25 43.37,11.28 43.37,11.68 Q9.2 ; J25.2 51.34,11.29 50.98,11.65 50.98,12.48 C138.2 ; J25.4 47.34,11.02 47.37,11.05
LVDS_VIO_: length 8.7
  TOP w0.432: J26.1 40.09,9.14 ; J26.1 39.17,10.07 ; J26.1 38.24,9.14 ; J26.1 39.17,8.22 ; 37.99,9.14 J26.3 37.17,9.97 ; J26.2 39.99,7.14 ; J26.2 38.34,7.14 ; J26.2 39.17,7.97 ; J26.2 39.17,6.32
MIC1_INN: length 62.9
  TOP w0.254: v2(89.66,19.15) 88.96,19.15 88.58,19.53 86.51,19.53 85.64,18.67 84.07,18.67 83.29,19.46 67.54,19.46 65.66,21.34 60.68,21.34 59.96,22.05 49.64,22.05 49.39,22.3 M5.13 ; J15.4 94,5.57 92.2,7.37 92.2,11.99 90.38,13.82 D41.1 R68.1 v2(89.66,14.99) R70.1
  BOTTOM w0.254: v2(89.66,14.99) 89.28,15.37 89.28,18.77 v2(89.66,19.15)
MIC1_INP: length 111.9
  TOP w0.254: v2(88.39,19.08) 86.59,19.08 85.8,18.29 83.82,18.29 83.03,19.08 67.28,19.08 65.41,20.95 60.52,20.95 59.81,21.67 49.33,21.67 48.39,22.6 M5.12
  TOP w0.305: J16.2 134.77,16.1 D42.1 134.83,17.45 C84.2 R78.2 v1(134.11,19.68)
  BOTTOM w0.254: v2(88.39,19.08) 88.39,12.73 94.37,6.76 94.59,6.76 94.64,6.71 102.97,6.71 105.03,8.76 125.76,8.76 134.11,17.11 v1(134.11,19.68)
MIPI_CAM0_PDN_L_GPIO2_C1: length 115.3
  TOP w0.127: M5.53 89.39,24 v2(88.87,24.51) ; v2(23.04,64.06) 21.97,62.99 21.08,62.99 20.91,62.82 R142.1 ; v2(39.62,68.33) 38.1,66.8 38.1,62.28 38.89,61.49 72.11,61.49 76.83,56.77 76.83,31.5 v2(76.33,30.99)
  BOTTOM w0.127: v2(88.87,24.51) 88.87,25.04 88.39,25.53 88.39,26.16 87.38,27.18 84.69,27.18 84.46,27.18 82.42,29.21 78.11,29.21 v2(76.33,30.99) ; v2(39.62,68.33) 38.1,69.85 37.47,69.85 36.32,70.99 28.45,70.99 23.04,65.58 v2(23.04,64.06)
MIPI_CSI_CLKN: length 4.6
  TOP w0.102: J28.17 25.25,65.8 25.17,65.92 25.2,66.09 25.3,66.19 26.74,66.19 27.36,66.81 27.56,66.81 27.66,66.71 27.66,66.52 27.76,66.42 R141.2
MIPI_CSI_CLKP: length 4.7
  TOP w0.102: J28.18 25.08,66.3 25.2,66.42 26.64,66.42 27.26,67.04 27.56,67.04 27.66,67.14 27.66,67.34 27.76,67.44 R140.2
MIPI_CSI_D0N: length 4.8
  TOP w0.102: R133.2 27.76,62.23 27.66,62.33 27.66,62.52 27.56,62.62 27.2,62.62 26.64,63.18 25.15,63.18 25.02,63.04 25.02,62.9 25.15,62.77 25.94,62.77 J28.11
MIPI_CSI_D0P: length 4.7
  TOP w0.102: J28.12 24.12,63.41 26.74,63.41 27.29,62.85 27.56,62.85 27.66,62.95 27.66,63.14 27.76,63.25 R132.2
MIPI_CSI_D1N: length 4.7
  TOP w0.102: R135.2 27.76,64.39 27.66,64.49 27.66,64.68 27.56,64.78 27.34,64.78 26.76,64.21 24.11,64.21 J28.14
MIPI_CSI_D1P: length 4.6
  TOP w0.102: J28.15 25.28,64.8 25.1,64.62 25.1,64.52 25.17,64.44 26.67,64.44 27.24,65.01 27.56,65.01 27.66,65.11 27.66,65.3 27.76,65.41 R134.2
MIPI_CSI_D2N: length 5.7
  TOP w0.102: J28.20 25.04,67.3 25.14,67.19 26.81,67.19 27.08,67.46 27.08,68.51 27.42,68.85 27.56,68.85 27.66,68.75 27.66,68.55 27.76,68.45 R137.2
MIPI_CSI_D2P: length 5.8
  TOP w0.102: R136.2 27.76,69.47 27.66,69.37 27.66,69.18 27.56,69.08 27.32,69.08 26.85,68.6 26.85,67.56 26.71,67.42 25.24,67.42 25.08,67.58 25.08,67.72 25.18,67.81 25.96,67.81 J28.21
MIPI_CSI_D3N: length 5.5
  TOP w0.102: R139.2 27.76,70.48 27.66,70.59 27.66,70.78 27.56,70.88 27.16,70.88 27.05,70.77 27.05,70.23 26.34,69.52 25.42,69.52 25.15,69.25 25.15,68.93 25.27,68.8 J28.23
MIPI_CSI_D3P: length 5.5
  TOP w0.102: R138.2 27.76,71.5 27.66,71.4 27.66,71.21 27.56,71.11 27.06,71.11 26.82,70.87 26.82,70.33 26.25,69.75 25.32,69.75 24.88,69.3 J28.24
MIPI_CSI_RX_CLK0N: length 12.4
  TOP w0.102: R141.1 29.41,66.83 30.39,66.83 31.24,65.97 31.24,61.78 33.4,59.62 34.61,59.62 35,59.24 M5.170
MIPI_CSI_RX_CLK0P: length 12.4
  TOP w0.102: M5.169 34.99,60.24 34.6,59.85 33.49,59.85 31.47,61.87 31.47,66.07 30.48,67.06 29.39,67.06 R140.1
MIPI_CSI_RX_D0N: length 11.7
  TOP w0.102: M5.162 35,67.24 34.61,67.62 34.24,67.62 v2(34,67.38) ; v2(30.83,65.83) 30.58,65.58 30.58,63.47 29.73,62.62 29.4,62.62 R133.1
  BOTTOM w0.102: v2(30.83,65.83) 30.58,66.07 30.58,66.33 30.83,66.57 32.28,66.57 32.61,66.9 32.61,67.66 32.81,67.86 33.19,67.86 33.4,67.64 33.73,67.64 v2(34,67.38)
MIPI_CSI_RX_D0P: length 11.7
  TOP w0.102: M5.161 35.01,68.24 34.63,67.85 34.24,67.85 v2(34,68.1) ; v2(30.11,65.83) 30.35,65.58 30.35,63.57 29.64,62.85 29.4,62.85 R132.1
  BOTTOM w0.102: v2(34,68.1) 33.77,67.87 33.5,67.87 33.28,68.08 32.72,68.08 32.38,67.75 32.38,67 32.19,66.8 30.73,66.8 30.35,66.42 30.35,66.07 v2(30.11,65.83)
MIPI_CSI_RX_D1N: length 12.2
  TOP w0.102: v2(34.2,65.38) 34.44,65.62 34.61,65.62 34.99,65.24 M5.164 ; v2(29.86,64.54) 29.62,64.78 29.4,64.78 R135.1
  BOTTOM w0.102: v2(34.2,65.38) 34.02,65.56 33.69,65.56 33.43,65.81 31.75,65.81 31.62,65.68 31.62,65.43 31.75,65.3 33.11,65.3 33.38,65.04 33.38,64.52 33.11,64.26 31.37,64.26 30.85,64.78 30.1,64.78 v2(29.86,64.54)
MIPI_CSI_RX_D1P: length 12.3
  TOP w0.102: v2(34.2,66.1) 34.44,65.85 34.58,65.85 34.97,66.24 M5.163 ; v2(29.86,65.26) 29.62,65.01 29.4,65.01 R134.1
  BOTTOM w0.102: v2(34.2,66.1) 33.89,65.79 33.78,65.79 33.53,66.04 31.66,66.04 31.39,65.78 31.39,65.33 31.66,65.07 33.02,65.07 33.15,64.95 33.15,64.62 33.02,64.49 31.46,64.49 30.94,65.01 30.1,65.01 v2(29.86,65.26)
MIPI_CSI_RX_D2N: length 10.7
  TOP w0.102: M5.166 35.04,63.24 34.62,63.65 33.88,63.65 33.27,64.26 33.27,66.93 31.88,68.33 30.48,68.33 29.96,68.85 29.4,68.85 R137.1
MIPI_CSI_RX_D2P: length 10.6
  TOP w0.102: R136.1 29.4,69.08 30.05,69.08 30.57,68.55 31.97,68.55 33.5,67.02 33.5,64.36 33.98,63.88 34.65,63.88 35,64.24 M5.165
MIPI_CSI_RX_D3N: length 14.5
  TOP w0.102: v2(31.19,67.76) 31.43,67.51 31.43,67.25 32.28,66.4 32.28,62.97 33.63,61.62 34.64,61.62 35.03,61.24 M5.168 ; v2(31.18,68.96) 31.42,69.2 31.42,69.48 30.02,70.88 29.4,70.88 R139.1
  BOTTOM w0.102: v2(31.19,67.76) 31.43,68 31.43,68.7 v2(31.18,68.96)
MIPI_CSI_RX_D3P: length 14.5
  TOP w0.102: M5.167 35.03,62.24 34.65,61.85 33.72,61.85 32.51,63.06 32.51,66.49 31.66,67.34 31.66,67.51 v2(31.9,67.76) ; R138.1 29.4,71.11 30.11,71.11 31.65,69.57 31.65,69.2 v2(31.89,68.96)
  BOTTOM w0.102: v2(31.9,67.76) 31.66,68 31.66,68.72 v2(31.89,68.96)
MIPI_DSI_TX0_CLKN: length 73.6
  TOP w0.102: U17.19 22.31,26.6 22.44,26.74 22.44,26.94 23.85,28.35 25.17,28.35 25.63,28.8 25.68,28.8 26.16,29.29 v2(26.16,29.46) ; v2(42.03,66.17) 41.78,66.41 41.78,66.51 41.88,66.61 42.21,66.61 42.41,66.42 52.7,66.42 55,68.72 55,68.97 55.39,69.36 M5.142
  GND w0.102: v2(26.16,29.46) 25.96,29.26 25.78,29.26 25.65,29.39 25.65,30.99 27.01,32.35 27.16,32.35 27.29,32.21 27.69,32.21 28.01,32.53 28.01,32.93 27.87,33.07 27.87,33.21 28.02,33.35 28.16,33.35 28.36,33.15 28.76,33.15 29.08,33.48 29.08,33.87 28.88,34.07 28.88,34.21 29.02,34.36 29.17,34.36 29.43,34.1 29.83,34.1 30.15,34.42 30.15,34.81 29.89,35.08 29.89,35.22 30.05,35.38 31.95,35.38 41.83,45.26 41.83,46.61 42.8,47.57 42.8,64.95 42.09,65.66 41.98,65.66 41.82,65.82 41.82,65.96 v2(42.03,66.17)
  BOTTOM w0.102: v2(26.16,29.46) 26.41,29.22 26.56,29.22 26.82,28.96 26.82,28.8 27.47,28.16 27.47,27.82 R98.1
MIPI_DSI_TX0_CLKN_: length 5.6
  BOTTOM w0.102: J22.27 27.79,22.07 27.65,22.21 27.65,22.76 27.25,23.16 27.25,23.39 27.39,23.53 D53.9 D53.2 27.39,25.16 27.25,25.29 27.25,25.42 27.48,25.65 27.48,26.14 R98.2
MIPI_DSI_TX0_CLKP: length 73.4
  TOP w0.102: M5.143 54.39,69.36 54.77,68.97 54.77,68.81 52.61,66.65 52.31,66.65 52.18,66.78 51.87,66.78 51.75,66.65 51.44,66.65 51.31,66.78 51.01,66.78 50.88,66.65 50.58,66.65 50.45,66.78 50.15,66.78 50.02,66.65 42.5,66.65 42.31,66.84 41.79,66.84 41.55,66.61 41.55,66.41 v2(41.31,66.17) ; v2(26.16,28.75) 26.13,28.78 25.98,28.78 25.77,28.57 25.72,28.57 25.27,28.12 23.95,28.12 22.67,26.84 22.67,26.74 22.81,26.6 U17.18
  GND w0.102: v2(41.31,66.17) 41.52,65.96 41.52,65.69 41.85,65.35 41.96,65.35 42.49,64.82 42.49,47.7 41.53,46.74 41.53,45.39 31.83,35.69 29.92,35.69 29.58,35.35 29.58,34.95 29.84,34.69 29.84,34.54 29.7,34.4 29.56,34.4 29.29,34.66 28.9,34.66 28.58,34.34 28.58,33.94 28.78,33.75 28.78,33.6 28.63,33.46 28.49,33.46 28.29,33.66 27.89,33.66 27.57,33.34 27.57,32.94 27.71,32.8 27.71,32.66 27.56,32.52 27.42,32.52 27.28,32.65 26.89,32.65 25.35,31.11 25.35,29.26 25.65,28.95 25.96,28.95 v2(26.16,28.75)
  BOTTOM w0.102: v2(26.16,28.75) 26.41,28.99 26.46,28.99 26.59,28.86 26.59,28.71 27.24,28.06 27.24,27.82 R97.1
MIPI_DSI_TX0_CLKP_: length 5.6
  BOTTOM w0.102: J22.26 27.29,22.07 27.42,22.21 27.42,22.67 27.02,23.06 27.02,23.38 26.89,23.52 D53.10 D53.1 26.89,25.16 27.02,25.29 27.02,25.52 27.25,25.75 27.25,26.11 R97.2
MIPI_DSI_TX0_D0N: length 73
  TOP w0.102: v2(30.19,29.2) 29.93,28.95 29.71,28.95 28.78,28.02 27.44,28.02 26.45,27.03 24.74,27.03 24.44,26.73 24.44,26.47 24.31,26.33 U17.15 ; v2(44.03,68.2) 43.79,68.44 43.79,68.51 43.89,68.61 50.75,68.61 51,68.86 51,69.22 51.39,69.6 M5.146
  GND w0.102: v2(30.19,29.2) 29.98,28.99 29.68,28.99 29.46,29.21 29.46,30.43 30.4,31.37 31.35,31.37 31.92,30.79 32.32,30.79 32.64,31.12 32.64,31.51 31.67,32.49 31.67,32.63 31.81,32.78 31.95,32.78 32.93,31.8 33.32,31.8 33.65,32.12 33.65,32.52 32.67,33.49 32.67,33.64 39.88,40.84 42.49,40.84 44.37,42.72 44.37,67.3 43.83,67.85 43.83,67.99 v2(44.03,68.2)
  BOTTOM w0.102: v2(30.19,29.2) 30.43,28.96 30.8,28.96 31.69,28.07 31.69,27.77 R94.1
MIPI_DSI_TX0_D0N_: length 6.4
  BOTTOM w0.102: R94.2 31.69,26.18 31.69,25.92 31.37,25.6 30.88,25.6 30.66,25.38 30.66,24.28 D55.2 30.65,23.21 30.65,22.46 30.79,22.32 J22.33
MIPI_DSI_TX0_D0P: length 73.2
  TOP w0.102: M5.147 50.39,69.6 50.77,69.22 50.77,68.95 50.65,68.83 43.8,68.83 43.57,68.6 43.57,68.45 v2(43.32,68.2) ; U17.14 24.81,26.33 24.67,26.47 24.67,26.63 24.83,26.8 26.54,26.8 27.53,27.79 28.87,27.79 29.08,28 29.27,28 29.33,27.93 29.46,27.93 29.66,28.14 29.66,28.25 29.56,28.35 29.56,28.48 29.8,28.72 29.95,28.72 v2(30.19,28.48)
  GND w0.102: v2(30.19,28.48) 29.98,28.69 29.55,28.69 29.16,29.08 29.16,30.56 30.28,31.67 31.47,31.67 32.05,31.1 32.19,31.1 32.34,31.24 32.34,31.39 31.36,32.36 31.36,32.76 31.68,33.08 32.08,33.08 33.05,32.1 33.2,32.1 33.34,32.25 33.34,32.39 32.37,33.37 32.37,33.76 39.75,41.15 42.37,41.15 44.07,42.85 44.07,67.18 43.52,67.72 43.52,67.99 v2(43.32,68.2)
  BOTTOM w0.102: R93.1 31.46,27.77 31.46,27.98 30.71,28.73 30.43,28.73 v2(30.19,28.48)
MIPI_DSI_TX0_D0P_: length 6.4
  BOTTOM w0.102: J22.32 30.29,22.32 30.42,22.46 30.42,23.2 D54.2 30.43,24.31 30.43,25.48 30.78,25.83 31.27,25.83 31.46,26.02 31.46,26.18 R93.2
MIPI_DSI_TX0_D1N: length 72.9
  TOP w0.102: v2(28.01,29.3) 27.77,29.06 27.53,29.06 26.13,27.66 24.23,27.66 23.44,26.87 23.44,26.44 23.31,26.31 U17.17 ; v2(43.53,67.06) 43.28,67.3 43.28,67.47 43.4,67.59 52.01,67.59 53,68.58 53,69 53.39,69.39 M5.144
  GND w0.102: v2(28.01,29.3) 27.81,29.1 27.66,29.1 27.43,29.33 27.43,30.61 27.49,30.66 27.49,30.67 27.75,30.93 27.76,30.93 27.94,31.11 29.01,31.11 40.13,42.24 40.35,42.24 40.84,41.74 41.24,41.74 41.56,42.07 41.56,42.46 41.07,42.95 41.07,43.1 41.21,43.24 41.35,43.24 41.85,42.75 42.24,42.75 42.56,43.07 42.56,43.47 42.07,43.96 42.07,44.1 42.22,44.25 42.36,44.25 42.85,43.76 43.25,43.76 43.57,44.08 43.57,44.47 43.08,44.97 43.08,45.11 43.61,45.64 43.61,66.37 43.32,66.66 43.32,66.85 v2(43.53,67.06)
  BOTTOM w0.102: R96.1 29.62,27.81 29.62,28.24 28.8,29.06 28.26,29.06 v2(28.01,29.3)
MIPI_DSI_TX0_D1N_: length 6.1
  BOTTOM w0.102: R96.2 29.59,26.11 29.59,25.93 29.31,25.65 28.9,25.65 28.75,25.51 28.75,25.29 28.89,25.16 D53.5 D53.6 28.89,23.55 28.75,23.41 28.75,23.13 29.15,22.74 29.15,22.15 29.29,22.01 J22.30
MIPI_DSI_TX0_D1P: length 73
  TOP w0.102: v2(42.81,67.06) 43.05,67.3 43.05,67.56 43.31,67.82 48.46,67.82 48.59,67.94 48.9,67.94 49.02,67.82 49.33,67.82 49.45,67.94 49.76,67.94 49.89,67.82 50.19,67.82 50.32,67.94 50.62,67.94 50.75,67.82 51.92,67.82 52.77,68.67 52.77,69.02 52.39,69.4 M5.145 ; v2(28.01,28.59) 27.77,28.83 27.63,28.83 26.23,27.43 24.32,27.43 23.67,26.78 23.67,26.45 23.81,26.31 U17.16
  GND w0.102: v2(42.81,67.06) 43.01,66.85 43.01,66.54 43.31,66.24 43.31,45.77 42.77,45.24 42.77,44.84 43.27,44.35 43.27,44.2 43.12,44.06 42.98,44.06 42.49,44.55 42.09,44.55 41.77,44.23 41.77,43.83 42.26,43.34 42.26,43.2 42.12,43.06 41.97,43.06 41.48,43.55 41.08,43.55 40.76,43.22 40.76,42.83 41.25,42.34 41.25,42.19 41.11,42.05 40.97,42.05 40.47,42.54 40,42.54 28.88,31.42 27.81,31.42 27.63,31.24 27.63,31.24 27.18,30.79 27.18,30.79 27.13,30.73 27.13,29.2 27.54,28.79 27.81,28.79 v2(28.01,28.59)
  BOTTOM w0.102: v2(28.01,28.59) 28.26,28.83 28.7,28.83 29.39,28.14 29.39,27.84 R95.1
MIPI_DSI_TX0_D1P_: length 6.1
  BOTTOM w0.102: R95.2 29.36,26.14 29.36,26.03 29.22,25.88 28.8,25.88 28.52,25.6 28.52,25.29 28.39,25.16 D53.4 D53.7 28.39,23.52 28.52,23.38 28.52,23.04 28.92,22.64 28.92,22.17 28.79,22.04 J22.29
MIPI_DSI_TX0_D2N: length 73.1
  TOP w0.102: v2(24.26,29.45) 24.01,29.21 23.72,29.21 21.44,26.93 21.44,26.74 21.31,26.6 U17.21 ; v2(41.14,65.02) 40.89,65.27 40.89,65.37 41,65.47 41.39,65.47 41.56,65.3 52.8,65.3 55.85,68.35 56.54,68.35 57,68.81 57,69.07 57.39,69.45 M5.140
  GND w0.102: v2(24.26,29.45) 24.05,29.25 23.91,29.25 23.67,29.48 23.67,30.86 29.46,36.65 31.88,36.65 40.77,45.54 40.77,47.32 41.96,48.51 41.96,64.14 41.53,64.57 41.03,64.57 40.93,64.67 40.93,64.82 v2(41.14,65.02)
  BOTTOM w0.102: R100.1 25.34,27.82 25.34,28.2 24.99,28.55 24.99,28.98 24.79,29.18 24.53,29.18 v2(24.26,29.45)
MIPI_DSI_TX0_D2N_: length 5.7
  BOTTOM w0.102: J22.24 26.29,22.04 26.15,22.17 26.15,22.74 25.86,23.03 25.86,23.45 25.99,23.59 D52.6 D52.5 25.99,24.91 25.83,25.07 25.83,25.39 25.35,25.88 25.35,26.14 R100.2
MIPI_DSI_TX0_D2P: length 73.2
  TOP w0.102: v2(24.26,28.74) 24.01,28.98 23.82,28.98 21.67,26.83 21.67,26.74 21.81,26.6 U17.20 ; M5.141 56.39,69.43 56.77,69.05 56.77,68.91 56.45,68.58 55.75,68.58 52.7,65.53 52.4,65.53 52.27,65.66 51.97,65.66 51.84,65.53 51.54,65.53 51.41,65.66 51.1,65.66 50.98,65.53 50.67,65.53 50.55,65.66 50.24,65.66 50.11,65.53 41.66,65.53 41.49,65.7 40.9,65.7 40.67,65.46 40.67,65.27 v2(40.42,65.02)
  GND w0.102: v2(40.42,65.02) 40.63,64.82 40.63,64.55 40.91,64.27 41.4,64.27 41.66,64.01 41.66,48.64 40.46,47.45 40.46,45.67 31.75,36.96 29.34,36.96 23.37,30.99 23.37,29.36 23.78,28.94 24.05,28.94 v2(24.26,28.74)
  BOTTOM w0.102: R99.1 25.11,27.82 25.11,28.11 24.76,28.45 24.76,28.89 24.7,28.96 24.48,28.96 v2(24.26,28.74)
MIPI_DSI_TX0_D2P_: length 5.7
  BOTTOM w0.102: R99.2 25.12,26.11 25.12,25.78 25.6,25.3 25.6,25.08 25.49,24.97 D52.4 D52.7 25.49,23.58 25.63,23.44 25.63,22.94 25.92,22.64 25.92,22.21 25.79,22.07 J22.23
MIPI_DSI_TX0_D3N: length 73.3
  TOP w0.102: U17.23 20.31,26.6 20.44,26.74 20.44,27.11 21.21,27.88 21.21,28.32 21.95,29.06 22.21,29.06 v2(22.45,29.3) ; M5.138 59.39,69.47 59,69.09 59,68.78 57.78,67.56 56.2,67.56 52.9,64.26 41.02,64.26 40.92,64.16 40.92,64 v2(41.16,63.75)
  GND w0.102: v2(41.16,63.75) 40.96,63.55 40.96,48.7 39.88,47.62 39.88,45.97 31.45,37.54 28.96,37.54 21.97,30.56 21.97,29.2 22.07,29.1 22.25,29.1 v2(22.45,29.3)
  BOTTOM w0.102: R101.1 23.2,27.82 23.2,28.87 22.99,29.08 22.67,29.08 v2(22.45,29.3)
MIPI_DSI_TX0_D3N_: length 6.3
  BOTTOM w0.102: R101.2 23.2,26.13 23.2,25.95 23.39,25.76 23.93,25.76 24.36,25.32 24.36,25.05 24.49,24.92 D52.2 D52.9 24.49,23.53 24.36,23.39 24.36,22.66 24.65,22.36 24.65,22.17 24.79,22.04 J22.21
MIPI_DSI_TX0_D3P: length 73.4
  TOP w0.102: v2(40.45,63.75) 40.69,64 40.69,64.26 40.93,64.49 50.22,64.49 50.34,64.62 50.65,64.62 50.77,64.49 51.08,64.49 51.21,64.62 51.51,64.62 51.64,64.49 51.94,64.49 52.07,64.62 52.37,64.62 52.5,64.49 52.81,64.49 56.11,67.79 57.69,67.79 58.77,68.88 58.77,69.09 58.39,69.47 M5.139 ; v2(22.45,28.59) 22.21,28.83 22.04,28.83 21.44,28.23 21.44,27.79 20.67,27.02 20.67,26.74 20.81,26.6 U17.22
  GND w0.102: v2(40.45,63.75) 40.65,63.55 40.65,48.83 39.57,47.75 39.57,46.1 31.32,37.85 28.83,37.85 21.67,30.68 21.67,29.07 21.95,28.79 22.25,28.79 v2(22.45,28.59)
  BOTTOM w0.102: v2(22.45,28.59) 22.72,28.85 22.89,28.85 22.97,28.77 22.97,27.82 R92.1
MIPI_DSI_TX0_D3P_: length 6.3
  BOTTOM w0.102: J22.20 24.29,22.07 24.42,22.21 24.42,22.27 24.13,22.56 24.13,23.38 23.99,23.52 D52.10 D52.1 23.99,24.91 24.13,25.04 24.13,25.23 23.83,25.53 23.3,25.53 22.97,25.85 22.97,26.13 R92.2
MIPI_DSI_TX0_RST: length 5.4
  BOTTOM w0.127: J22.36 32.29,23.66 C118.2 33.22,24.6 R103.2
MIPI_DSI_TX1_CLKN: length 65.3
  TOP w0.102: v2(57.02,66.33) 57.27,66.57 61.75,66.57 63.88,68.71 64.64,68.71 65,69.07 65,69.34 65.39,69.73 M5.132
  BOTTOM w0.102: v2(57.02,66.33) 56.8,66.55 56.72,66.55 56.62,66.45 56.62,64.74 53.34,61.47 53.34,44.7 57.4,40.64 57.4,33.17 57.02,32.79 56.01,32.79 55.88,32.66 55.88,32.36 56.01,32.23 56.99,32.23 57.25,31.97 57.25,31.53 56.99,31.27 55.98,31.27 55.85,31.14 55.85,30.86 55.98,30.73 57.02,30.73 57.28,30.48 57.28,30.03 56.99,29.74 55.97,29.74 55.85,29.62 55.85,27.33 57.28,25.91 57.28,25.6 57.41,25.46 D58.2 D58.9 57.41,23.61 57.28,23.48 57.28,23.05 57.37,22.95 57.37,22.46 57.51,22.32 J23.27
MIPI_DSI_TX1_CLKP: length 65.3
  TOP w0.102: v2(57.02,67.05) 57.27,66.8 61.65,66.8 63.79,68.94 64.55,68.94 64.77,69.16 64.77,69.34 64.39,69.72 M5.133
  BOTTOM w0.102: J23.26 57.01,22.32 57.14,22.46 57.14,22.86 57.05,22.95 57.05,23.48 56.91,23.61 D58.10 D58.1 56.91,25.46 57.05,25.6 57.05,25.81 55.63,27.24 55.63,29.72 55.88,29.97 56.9,29.97 57.05,30.12 57.05,30.39 56.93,30.51 55.89,30.51 55.63,30.77 55.63,31.24 55.89,31.5 56.9,31.5 57.02,31.62 57.02,31.88 56.9,32 55.91,32 55.65,32.26 55.65,32.76 55.91,33.02 56.93,33.02 57.18,33.27 57.18,40.55 53.11,44.61 53.11,61.56 56.39,64.84 56.39,66.54 56.62,66.78 56.75,66.78 v2(57.02,67.05)
MIPI_DSI_TX1_D0N: length 64.8
  TOP w0.102: M5.136 61.39,69.39 61,69 61,68.78 v2(61.25,68.54)
  BOTTOM w0.102: J23.33 60.51,22.32 60.37,22.46 60.37,22.84 60.58,23.04 60.58,23.35 D61.2 60.63,24.41 60.63,25.88 60.37,26.14 59.69,26.14 59.56,26.26 59.56,26.57 59.69,26.7 60.42,26.7 60.68,26.96 60.68,27.4 60.42,27.66 59.69,27.66 59.56,27.79 59.56,28.09 59.69,28.22 60.42,28.22 60.68,28.48 60.68,28.92 60.42,29.18 58.93,29.18 58.78,29.34 58.78,29.59 58.9,29.72 60.32,29.72 60.58,29.98 60.58,30.45 60.32,30.71 58.93,30.71 58.8,30.84 58.8,31.11 58.93,31.24 60.33,31.24 60.58,31.5 60.58,31.97 60.32,32.23 59.03,32.23 58.93,32.33 58.93,41.15 54.86,45.21 54.86,60.83 61,66.97 61,68.29 v2(61.25,68.54)
MIPI_DSI_TX1_D0P: length 64.8
  TOP w0.102: v2(60.53,68.54) 60.77,68.78 60.77,69.02 60.39,69.41 M5.137
  BOTTOM w0.102: v2(60.53,68.54) 60.77,68.3 60.77,67.06 54.64,60.93 54.64,45.12 58.7,41.05 58.7,32.24 58.93,32 60.22,32 60.35,31.88 60.35,31.59 60.23,31.47 58.83,31.47 58.57,31.21 58.57,30.74 58.83,30.48 60.22,30.48 60.35,30.35 60.35,30.07 60.22,29.95 58.81,29.95 58.55,29.69 58.55,29.24 58.83,28.96 60.33,28.96 60.45,28.83 60.45,28.57 60.33,28.45 59.6,28.45 59.33,28.19 59.33,27.69 59.6,27.43 60.33,27.43 60.45,27.3 60.45,27.05 60.33,26.92 59.6,26.92 59.33,26.66 59.33,26.17 59.6,25.91 60.27,25.91 60.4,25.78 60.4,24.41 D59.2 60.35,23.45 60.35,23.14 60.14,22.93 60.14,22.46 60.01,22.32 J23.32
MIPI_DSI_TX1_D1N: length 63.7
  TOP w0.102: M5.134 63.39,69.73 63,69.34 63,69.1 61.34,67.43 59.17,67.43 v2(58.93,67.19)
  BOTTOM w0.102: v2(58.93,67.19) 58.68,67.44 58.14,67.44 58.04,67.34 58.04,66.88 58.14,66.78 58.77,66.78 59.03,66.52 59.03,66.07 58.77,65.81 57.81,65.81 57.38,65.38 57.38,64.36 54.1,61.09 54.1,44.96 58.17,40.89 58.17,29.52 57.63,28.98 56.74,28.98 56.62,28.86 56.62,28.54 56.74,28.42 58.51,28.42 58.78,28.16 58.78,27.72 58.51,27.46 57.33,27.46 57.2,27.33 57.2,27.07 57.33,26.95 58.5,26.95 58.78,26.67 58.78,25.6 58.91,25.46 D58.5 D58.6 58.91,23.61 58.78,23.48 58.78,23.21 58.87,23.12 58.87,22.46 59,22.32 J23.30
MIPI_DSI_TX1_D1P: length 63.7
  TOP w0.102: M5.135 62.39,69.69 62.77,69.31 62.77,69.19 61.24,67.66 59.17,67.66 v2(58.93,67.91)
  BOTTOM w0.102: J23.29 58.5,22.32 58.64,22.46 58.64,23.02 58.55,23.11 58.55,23.48 58.41,23.61 D58.7 D58.4 58.41,25.46 58.55,25.6 58.55,26.58 58.4,26.72 57.23,26.72 56.97,26.98 56.97,27.43 57.23,27.69 58.42,27.69 58.55,27.81 58.55,28.07 58.42,28.19 56.64,28.19 56.39,28.45 56.39,28.96 56.64,29.21 57.53,29.21 57.94,29.62 57.94,40.8 53.87,44.86 53.87,61.18 57.15,64.46 57.15,65.47 57.72,66.04 58.67,66.04 58.8,66.17 58.8,66.42 58.67,66.55 58.05,66.55 57.81,66.78 57.81,67.43 58.05,67.67 58.69,67.67 v2(58.93,67.91)
MIPI_DSI_TX1_D2N: length 65.1
  TOP w0.102: M5.130 67.39,69.73 67,69.34 67,69.16 65.66,67.82 64.26,67.82 62,65.56 55.86,65.56 v2(55.63,65.32)
  BOTTOM w0.102: J23.24 56,22.32 55.87,22.46 55.87,23.46 56.02,23.61 D57.6 D57.5 56.02,25.46 55.88,25.6 55.88,26.03 55.09,26.82 55.09,33.4 55.22,33.53 56.23,33.53 56.49,33.79 56.49,34.28 56.23,34.54 55.24,34.54 55.12,34.67 55.12,34.92 55.24,35.05 56.26,35.05 56.64,35.43 56.64,40.39 52.58,44.45 52.58,61.78 55.09,64.29 55.09,65.31 55.29,65.51 55.44,65.51 v2(55.63,65.32)
